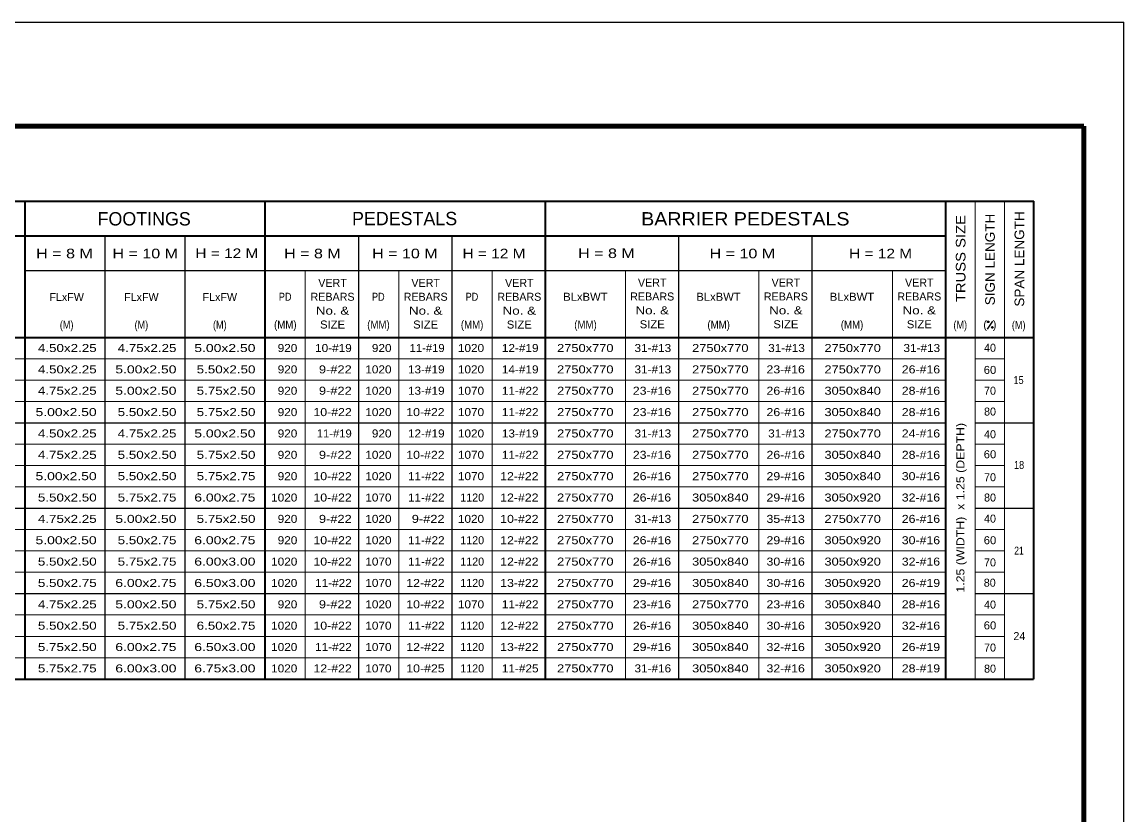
# Model space of a CAD drawing. Extents: x 312601.858 to 312602.699, y 144420.11 to 144420.704.
# Drawn here: x 312602.2859 to 312602.6989, y 144420.4066 to 144420.7036 of the extents above; entities that cross this region are included whole.
import ezdxf
from ezdxf.enums import TextEntityAlignment as Align

# ---------------------------------------------------------------- set-up
doc = ezdxf.new("R2010")
doc.units = 0
doc.header["$LTSCALE"] = 0.0012
for name, color, linetype, lineweight in [('1', 7, 'Continuous', 25), ('2', 7, 'Continuous', 13), ('39', 7, 'Continuous', 13)]:
    doc.layers.add(name, color=color, linetype=linetype, lineweight=lineweight)

msp = doc.modelspace()

# ---------------------------------------------------------------- linework, layer by layer
at = {"layer": '1', "lineweight": 35}
for p, q in [((312601.9241, 144420.6365), (312602.6651, 144420.6365)), ((312602.2871, 144420.4575), (312602.2871, 144420.6365)), ((312602.3771, 144420.4575), (312602.3771, 144420.6365)), ((312602.4821, 144420.4575), (312602.4821, 144420.6365)), ((312602.6321, 144420.4575), (312602.6321, 144420.6365)), ((312602.6651, 144420.4575), (312602.6651, 144420.6365)), ((312601.9571, 144420.6235), (312602.6321, 144420.6235)), ((312601.9241, 144420.5855), (312602.6651, 144420.5855)), ((312601.9241, 144420.4575), (312602.665, 144420.4575))]:
    msp.add_line(p, q, dxfattribs=at)
at = {"layer": '1', "lineweight": 13}
for p, q in [((312602.6431, 144420.4575), (312602.6431, 144420.6365)), ((312602.6541, 144420.4575), (312602.6541, 144420.6365)), ((312602.3921, 144420.4575), (312602.3921, 144420.6105)), ((312602.4271, 144420.4575), (312602.4271, 144420.6105)), ((312602.4621, 144420.4575), (312602.4621, 144420.6105)), ((312602.5121, 144420.4575), (312602.5121, 144420.6105)), ((312602.5621, 144420.4575), (312602.5621, 144420.6105)), ((312602.6121, 144420.4575), (312602.6121, 144420.6105)), ((312601.9571, 144420.5775), (312602.6321, 144420.5775)), ((312602.6431, 144420.5775), (312602.6541, 144420.5775)), ((312601.9573, 144420.5695), (312602.6321, 144420.5695)), ((312602.6431, 144420.5695), (312602.6541, 144420.5695)), ((312601.9573, 144420.5615), (312602.6321, 144420.5615)), ((312602.6431, 144420.5615), (312602.6541, 144420.5615)), ((312601.9573, 144420.5455), (312602.6321, 144420.5455)), ((312602.6431, 144420.5455), (312602.6541, 144420.5455)), ((312601.9573, 144420.5375), (312602.6321, 144420.5375)), ((312602.6431, 144420.5375), (312602.6541, 144420.5375)), ((312601.9573, 144420.5295), (312602.6321, 144420.5295)), ((312602.6431, 144420.5295), (312602.6541, 144420.5295)), ((312601.9573, 144420.5135), (312602.6321, 144420.5135)), ((312602.6431, 144420.5135), (312602.6541, 144420.5135)), ((312601.9573, 144420.5055), (312602.6321, 144420.5055)), ((312602.6431, 144420.5055), (312602.6541, 144420.5055)), ((312601.9573, 144420.4975), (312602.6321, 144420.4975)), ((312602.6431, 144420.4975), (312602.6541, 144420.4975)), ((312601.9573, 144420.4815), (312602.6321, 144420.4815)), ((312602.6431, 144420.4815), (312602.6541, 144420.4815)), ((312601.9573, 144420.4735), (312602.6321, 144420.4735)), ((312602.6431, 144420.4735), (312602.6541, 144420.4735)), ((312601.9573, 144420.4655), (312602.6321, 144420.4655)), ((312602.6431, 144420.4655), (312602.6541, 144420.4655))]:
    msp.add_line(p, q, dxfattribs=at)
at = {"layer": '1'}
for p, q in [((312602.3171, 144420.4575), (312602.3171, 144420.6235)), ((312602.3471, 144420.4575), (312602.3471, 144420.6235)), ((312602.4121, 144420.4575), (312602.4121, 144420.6235)), ((312602.4471, 144420.4575), (312602.4471, 144420.6235)), ((312602.5321, 144420.4575), (312602.5321, 144420.6235)), ((312602.5821, 144420.4575), (312602.5821, 144420.6235)), ((312602.2871, 144420.6105), (312602.6321, 144420.6105)), ((312602.6477, 144420.5886), (312602.6497, 144420.5916)), ((312601.9573, 144420.5535), (312602.6321, 144420.5535)), ((312602.6431, 144420.5535), (312602.6651, 144420.5535)), ((312601.9573, 144420.5215), (312602.6321, 144420.5215)), ((312602.6431, 144420.5215), (312602.6651, 144420.5215)), ((312601.9573, 144420.4895), (312602.6321, 144420.4895)), ((312602.6431, 144420.4895), (312602.6651, 144420.4895))]:
    msp.add_line(p, q, dxfattribs=at)
for centre in [(312602.648, 144420.5913), (312602.6496, 144420.5892)]:
    msp.add_circle(centre, 0.0003, dxfattribs=at)
at = {"layer": '39', "lineweight": 25}
for p, q in [((312601.8579, 144420.7036), (312602.6989, 144420.7036)), ((312602.5736, 144420.6646), (312602.6839, 144420.6646)), ((312602.6839, 144420.6515), (312602.6839, 144420.6646))]:
    msp.add_line(p, q, dxfattribs=at)
msp.add_lwpolyline([(312601.8579, 144420.1096), (312602.6989, 144420.1096), (312602.6989, 144420.7036)], dxfattribs=at)
at = {"layer": '39', "lineweight": 158}
for points in [[(312601.9089, 144420.1246), (312602.6839, 144420.1246), (312602.6839, 144420.6646)], [(312601.9089, 144420.1248), (312601.9089, 144420.6646), (312602.6839, 144420.6646)]]:
    msp.add_lwpolyline(points, dxfattribs=at)

# ---------------------------------------------------------------- texts
at = {"layer": '1'}
for s, height, p in [('PEDESTALS', 0.005, (312602.4293, 144420.6275)), ('FOOTINGS', 0.005, (312602.3317, 144420.6274)), ('VERT', 0.003, (312602.4023, 144420.6044)), ('VERT', 0.003, (312602.4372, 144420.6044)), ('VERT', 0.003, (312602.4723, 144420.6044)), ('VERT', 0.003, (312602.5221, 144420.6045)), ('VERT', 0.003, (312602.5722, 144420.6045)), ('VERT', 0.003, (312602.6222, 144420.6045)), ('FLxFW', 0.003, (312602.30265, 144420.5991)), ('FLxFW', 0.003, (312602.33065, 144420.5991)), ('FLxFW', 0.003, (312602.36005, 144420.5991)), ('REBARS', 0.003, (312602.4023, 144420.5992)), ('REBARS', 0.003, (312602.4372, 144420.5992)), ('REBARS', 0.003, (312602.4723, 144420.5992)), ('REBARS', 0.003, (312602.5221, 144420.5993)), ('REBARS', 0.003, (312602.5722, 144420.5993)), ('REBARS', 0.003, (312602.6222, 144420.5993)), ('(  )', 0.003, (312602.64865, 144420.5888)), ('40', 0.003, (312602.6487, 144420.5801)), ('70', 0.003, (312602.6487, 144420.564)), ('80', 0.003, (312602.6487, 144420.5562)), ('40', 0.003, (312602.6487, 144420.5477)), ('70', 0.003, (312602.6487, 144420.5316)), ('80', 0.003, (312602.6487, 144420.524)), ('40', 0.003, (312602.6487, 144420.5161)), ('70', 0.003, (312602.6487, 144420.4997)), ('80', 0.003, (312602.6486, 144420.4921)), ('40', 0.003, (312602.6487, 144420.4839)), ('24', 0.003, (312602.6597, 144420.4721)), ('70', 0.003, (312602.6487, 144420.4678)), ('80', 0.003, (312602.6487, 144420.4599))]:
    msp.add_text(s, height=height, dxfattribs=at).set_placement(p, align=Align.CENTER)
for s, height, width, p in [('BARRIER PEDESTALS', 0.005, 1.1, (312602.557, 144420.6274)), ('H = 8 M', 0.0036, 1.25, (312602.30185, 144420.6151)), ('H = 10 M', 0.0036, 1.25, (312602.3321, 144420.6151)), ('H = 12 M', 0.0036, 1.2, (312602.3627, 144420.6152)), ('H = 8 M', 0.0036, 1.25, (312602.39475, 144420.6151)), ('H = 10 M', 0.0036, 1.25, (312602.4294, 144420.6151)), ('H = 12 M', 0.0036, 1.2, (312602.4628, 144420.6151)), ('H = 8 M', 0.0036, 1.25, (312602.50495, 144420.6152)), ('H = 10 M', 0.0036, 1.25, (312602.5559, 144420.6151)), ('H = 12 M', 0.0036, 1.2, (312602.6077, 144420.6151)), ('PD', 0.003, 0.85, (312602.38455, 144420.5992)), ('PD', 0.003, 0.85, (312602.41945, 144420.5992)), ('PD', 0.003, 0.85, (312602.45455, 144420.5992)), ('BLxBWT', 0.003, 1.05, (312602.49705, 144420.5992)), ('BLxBWT', 0.003, 1.05, (312602.54695, 144420.5992)), ('BLxBWT', 0.003, 1.05, (312602.59695, 144420.5992)), ('No. &', 0.003, 1.25, (312602.4023, 144420.594)), ('No. &', 0.003, 1.25, (312602.4372, 144420.594)), ('No. &', 0.003, 1.25, (312602.4723, 144420.594)), ('No. &', 0.003, 1.25, (312602.5221, 144420.5941)), ('No. &', 0.003, 1.25, (312602.5722, 144420.5941)), ('No. &', 0.003, 1.25, (312602.6222, 144420.5941)), ('(M)', 0.003, 0.85, (312602.30265, 144420.5887)), ('(M)', 0.003, 0.85, (312602.33065, 144420.5887)), ('(M)', 0.003, 0.85, (312602.36005, 144420.5887)), ('(MM)', 0.003, 0.9, (312602.3846, 144420.5888)), ('SIZE', 0.003, 1.05, (312602.4023, 144420.5888)), ('(MM)', 0.003, 0.9, (312602.4195, 144420.5888)), ('SIZE', 0.003, 1.05, (312602.4372, 144420.5888)), ('(MM)', 0.003, 0.9, (312602.4546, 144420.5888)), ('SIZE', 0.003, 1.05, (312602.4723, 144420.5888)), ('(MM)', 0.003, 0.9, (312602.4971, 144420.5888)), ('SIZE', 0.003, 1.05, (312602.5221, 144420.5889)), ('(MM)', 0.003, 0.9, (312602.547, 144420.5888)), ('SIZE', 0.003, 1.05, (312602.5722, 144420.5889)), ('(MM)', 0.003, 0.9, (312602.597, 144420.5888)), ('SIZE', 0.003, 1.05, (312602.6222, 144420.5889)), ('(M)', 0.003, 0.85, (312602.63755, 144420.5887)), ('(M)', 0.003, 0.85, (312602.65945, 144420.5886)), ('60', 0.003, 1.05, (312602.6487, 144420.5718)), ('15', 0.003, 0.85, (312602.6594, 144420.568)), ('60', 0.003, 1.05, (312602.6487, 144420.5402)), ('18', 0.003, 0.85, (312602.6596, 144420.5362)), ('60', 0.003, 1.05, (312602.6487, 144420.508)), ('21', 0.003, 0.8, (312602.65955, 144420.5041)), ('60', 0.003, 1.05, (312602.6487, 144420.4761))]:
    msp.add_text(s, height=height, dxfattribs=dict(at, width=width)).set_placement(p, align=Align.CENTER)
for s, height, width, p in [('TRUSS SIZE', 0.0036, 1.15, (312602.6395, 144420.615)), ('SIGN LENGTH', 0.0036, 1.05, (312602.6505, 144420.61465)), ('SPAN LENGTH', 0.0036, 1.05, (312602.6615, 144420.61485)), ('1.25 (WIDTH)  x 1.25 (DEPTH) ', 0.003, 1.15, (312602.6391, 144420.5223))]:
    msp.add_text(s, height=height, rotation=90, dxfattribs=dict(at, width=width)).set_placement(p, align=Align.CENTER)
at = {"layer": '2'}
for s, width, p in [('4.50x2.25', 1.25, (312602.3139, 144420.58)), ('4.75x2.25', 1.25, (312602.3438, 144420.58)), ('5.00x2.50', 1.3, (312602.3734, 144420.58)), ('920', 1.1, (312602.3891, 144420.58)), ('10-#19', 1.1, (312602.4095, 144420.58)), ('920', 1.1, (312602.4244, 144420.58)), ('11-#19', 1.05, (312602.4443, 144420.58)), ('1020', 1.1, (312602.4591, 144420.58)), ('12-#19', 1.1, (312602.4795, 144420.58)), ('2750x770', 1.2, (312602.5076, 144420.58)), ('31-#13', 1.1, (312602.5292, 144420.58)), ('2750x770', 1.2, (312602.5582, 144420.58)), ('31-#13', 1.1, (312602.5793, 144420.58)), ('2750x770', 1.2, (312602.6078, 144420.58)), ('31-#13', 1.1, (312602.63, 144420.58)), ('4.50x2.25', 1.25, (312602.3139, 144420.572)), ('5.00x2.50', 1.3, (312602.3438, 144420.572)), ('5.50x2.50', 1.25, (312602.3734, 144420.572)), ('920', 1.1, (312602.3891, 144420.572)), ('9-#22', 1.2, (312602.4095, 144420.572)), ('1020', 1.1, (312602.4244, 144420.572)), ('13-#19', 1.1, (312602.4443, 144420.572)), ('1020', 1.1, (312602.4591, 144420.572)), ('14-#19', 1.1, (312602.4795, 144420.572)), ('2750x770', 1.2, (312602.5076, 144420.572)), ('31-#13', 1.1, (312602.5292, 144420.572)), ('2750x770', 1.2, (312602.5582, 144420.572)), ('23-#16', 1.15, (312602.5793, 144420.572)), ('2750x770', 1.2, (312602.6078, 144420.572)), ('26-#16', 1.15, (312602.63, 144420.572)), ('4.75x2.25', 1.25, (312602.3139, 144420.564)), ('5.00x2.50', 1.3, (312602.3438, 144420.564)), ('5.75x2.50', 1.25, (312602.3734, 144420.564)), ('920', 1.1, (312602.3891, 144420.564)), ('9-#22', 1.2, (312602.4095, 144420.564)), ('1020', 1.1, (312602.4244, 144420.564)), ('13-#19', 1.1, (312602.4443, 144420.564)), ('1070', 1.1, (312602.4591, 144420.564)), ('11-#22', 1.1, (312602.4795, 144420.564)), ('2750x770', 1.2, (312602.5076, 144420.564)), ('23-#16', 1.15, (312602.5292, 144420.564)), ('2750x770', 1.2, (312602.5582, 144420.564)), ('26-#16', 1.15, (312602.5793, 144420.564)), ('3050x840', 1.2, (312602.6078, 144420.564)), ('28-#16', 1.15, (312602.63, 144420.564)), ('5.00x2.50', 1.3, (312602.3139, 144420.556)), ('5.50x2.50', 1.25, (312602.3438, 144420.556)), ('5.75x2.50', 1.25, (312602.3734, 144420.556)), ('920', 1.1, (312602.3891, 144420.556)), ('10-#22', 1.15, (312602.4095, 144420.556)), ('1020', 1.1, (312602.4244, 144420.556)), ('10-#22', 1.15, (312602.4443, 144420.556)), ('1070', 1.1, (312602.4591, 144420.556)), ('11-#22', 1.1, (312602.4795, 144420.556)), ('2750x770', 1.2, (312602.5076, 144420.556)), ('23-#16', 1.15, (312602.5292, 144420.556)), ('2750x770', 1.2, (312602.5582, 144420.556)), ('26-#16', 1.15, (312602.5793, 144420.556)), ('3050x840', 1.2, (312602.6078, 144420.556)), ('28-#16', 1.15, (312602.63, 144420.556)), ('4.50x2.25', 1.25, (312602.3139, 144420.548)), ('4.75x2.25', 1.25, (312602.3438, 144420.548)), ('5.00x2.50', 1.3, (312602.3734, 144420.548)), ('920', 1.1, (312602.3891, 144420.548)), ('11-#19', 1.05, (312602.4095, 144420.548)), ('920', 1.1, (312602.4244, 144420.548)), ('12-#19', 1.1, (312602.4443, 144420.548)), ('1020', 1.1, (312602.4591, 144420.548)), ('13-#19', 1.1, (312602.4795, 144420.548)), ('2750x770', 1.2, (312602.5076, 144420.548)), ('31-#13', 1.1, (312602.5292, 144420.548)), ('2750x770', 1.2, (312602.5582, 144420.548)), ('31-#13', 1.1, (312602.5793, 144420.548)), ('2750x770', 1.2, (312602.6078, 144420.548)), ('24-#16', 1.15, (312602.63, 144420.548)), ('4.75x2.25', 1.25, (312602.3139, 144420.54)), ('5.50x2.50', 1.25, (312602.3438, 144420.54)), ('5.75x2.50', 1.25, (312602.3734, 144420.54)), ('920', 1.1, (312602.3891, 144420.54)), ('9-#22', 1.2, (312602.4095, 144420.54)), ('1020', 1.1, (312602.4244, 144420.54)), ('10-#22', 1.15, (312602.4443, 144420.54)), ('1070', 1.1, (312602.4591, 144420.54)), ('11-#22', 1.1, (312602.4795, 144420.54)), ('2750x770', 1.2, (312602.5076, 144420.54)), ('23-#16', 1.15, (312602.5292, 144420.54)), ('2750x770', 1.2, (312602.5582, 144420.54)), ('26-#16', 1.15, (312602.5793, 144420.54)), ('3050x840', 1.2, (312602.6078, 144420.54)), ('28-#16', 1.15, (312602.63, 144420.54)), ('5.00x2.50', 1.3, (312602.3139, 144420.532)), ('5.50x2.50', 1.25, (312602.3438, 144420.532)), ('5.75x2.75', 1.25, (312602.3734, 144420.532)), ('920', 1.1, (312602.3891, 144420.532)), ('10-#22', 1.15, (312602.4095, 144420.532)), ('1020', 1.1, (312602.4244, 144420.532)), ('11-#22', 1.1, (312602.4443, 144420.532)), ('1070', 1.1, (312602.4591, 144420.532)), ('12-#22', 1.15, (312602.4795, 144420.532)), ('2750x770', 1.2, (312602.5076, 144420.532)), ('26-#16', 1.15, (312602.5292, 144420.532)), ('2750x770', 1.2, (312602.5582, 144420.532)), ('29-#16', 1.15, (312602.5793, 144420.532)), ('3050x840', 1.2, (312602.6078, 144420.532)), ('30-#16', 1.15, (312602.63, 144420.532)), ('5.50x2.50', 1.25, (312602.3139, 144420.524)), ('5.75x2.75', 1.25, (312602.3438, 144420.524)), ('6.00x2.75', 1.3, (312602.3734, 144420.524)), ('1020', 1.1, (312602.3891, 144420.524)), ('10-#22', 1.15, (312602.4095, 144420.524)), ('1070', 1.1, (312602.4244, 144420.524)), ('11-#22', 1.1, (312602.4443, 144420.524)), ('12-#22', 1.15, (312602.4795, 144420.524)), ('2750x770', 1.2, (312602.5076, 144420.524)), ('26-#16', 1.15, (312602.5292, 144420.524)), ('3050x840', 1.2, (312602.5582, 144420.524)), ('29-#16', 1.15, (312602.5793, 144420.524)), ('3050x920', 1.2, (312602.6078, 144420.524)), ('32-#16', 1.15, (312602.63, 144420.524)), ('4.75x2.25', 1.25, (312602.3139, 144420.516)), ('5.00x2.50', 1.3, (312602.3438, 144420.516)), ('5.75x2.50', 1.25, (312602.3734, 144420.516)), ('920', 1.1, (312602.3891, 144420.516)), ('9-#22', 1.2, (312602.4095, 144420.516)), ('1020', 1.1, (312602.4244, 144420.516)), ('9-#22', 1.2, (312602.4443, 144420.516)), ('1020', 1.1, (312602.4591, 144420.516)), ('10-#22', 1.15, (312602.4795, 144420.516)), ('2750x770', 1.2, (312602.5076, 144420.516)), ('31-#13', 1.1, (312602.5292, 144420.516)), ('2750x770', 1.2, (312602.5582, 144420.516)), ('35-#13', 1.15, (312602.5793, 144420.516)), ('2750x770', 1.2, (312602.6078, 144420.516)), ('26-#16', 1.15, (312602.63, 144420.516)), ('5.00x2.50', 1.3, (312602.3139, 144420.508)), ('5.50x2.75', 1.25, (312602.3438, 144420.508)), ('6.00x2.75', 1.3, (312602.3734, 144420.508)), ('920', 1.1, (312602.3891, 144420.508)), ('10-#22', 1.15, (312602.4095, 144420.508)), ('1020', 1.1, (312602.4244, 144420.508)), ('11-#22', 1.1, (312602.4443, 144420.508)), ('12-#22', 1.15, (312602.4795, 144420.508)), ('2750x770', 1.2, (312602.5076, 144420.508)), ('26-#16', 1.15, (312602.5292, 144420.508)), ('2750x770', 1.2, (312602.5582, 144420.508)), ('29-#16', 1.15, (312602.5793, 144420.508)), ('3050x920', 1.2, (312602.6078, 144420.508)), ('30-#16', 1.15, (312602.63, 144420.508)), ('5.50x2.50', 1.25, (312602.3139, 144420.5)), ('5.75x2.75', 1.25, (312602.3438, 144420.5)), ('6.00x3.00', 1.3, (312602.3734, 144420.5)), ('1020', 1.1, (312602.3891, 144420.5)), ('10-#22', 1.15, (312602.4095, 144420.5)), ('1070', 1.1, (312602.4244, 144420.5)), ('11-#22', 1.1, (312602.4443, 144420.5)), ('12-#22', 1.15, (312602.4795, 144420.5)), ('2750x770', 1.2, (312602.5076, 144420.5)), ('26-#16', 1.15, (312602.5292, 144420.5)), ('3050x840', 1.2, (312602.5582, 144420.5)), ('30-#16', 1.15, (312602.5793, 144420.5)), ('3050x920', 1.2, (312602.6078, 144420.5)), ('32-#16', 1.15, (312602.63, 144420.5)), ('5.50x2.75', 1.25, (312602.3139, 144420.492)), ('6.00x2.75', 1.3, (312602.3438, 144420.492)), ('6.50x3.00', 1.3, (312602.3734, 144420.492)), ('1020', 1.1, (312602.3891, 144420.492)), ('11-#22', 1.1, (312602.4095, 144420.492)), ('1070', 1.1, (312602.4244, 144420.492)), ('12-#22', 1.15, (312602.4443, 144420.492)), ('13-#22', 1.15, (312602.4795, 144420.492)), ('2750x770', 1.2, (312602.5076, 144420.492)), ('29-#16', 1.15, (312602.5292, 144420.492)), ('3050x840', 1.2, (312602.5582, 144420.492)), ('30-#16', 1.15, (312602.5793, 144420.492)), ('3050x920', 1.2, (312602.6078, 144420.492)), ('26-#19', 1.15, (312602.63, 144420.492)), ('4.75x2.25', 1.25, (312602.3139, 144420.484)), ('5.00x2.50', 1.3, (312602.3438, 144420.484)), ('5.75x2.50', 1.25, (312602.3734, 144420.484)), ('920', 1.1, (312602.3891, 144420.484)), ('9-#22', 1.2, (312602.4095, 144420.484)), ('1020', 1.1, (312602.4244, 144420.484)), ('10-#22', 1.15, (312602.4443, 144420.484)), ('1070', 1.1, (312602.4591, 144420.484)), ('11-#22', 1.1, (312602.4795, 144420.484)), ('2750x770', 1.2, (312602.5076, 144420.484)), ('23-#16', 1.15, (312602.5292, 144420.484)), ('2750x770', 1.2, (312602.5582, 144420.484)), ('23-#16', 1.15, (312602.5793, 144420.484)), ('3050x840', 1.2, (312602.6078, 144420.484)), ('28-#16', 1.15, (312602.63, 144420.484)), ('5.50x2.50', 1.25, (312602.3139, 144420.476)), ('5.75x2.50', 1.25, (312602.3438, 144420.476)), ('6.50x2.75', 1.25, (312602.3734, 144420.476)), ('1020', 1.1, (312602.3891, 144420.476)), ('10-#22', 1.15, (312602.4095, 144420.476)), ('1070', 1.1, (312602.4244, 144420.476)), ('11-#22', 1.1, (312602.4443, 144420.476)), ('12-#22', 1.15, (312602.4795, 144420.476)), ('2750x770', 1.2, (312602.5076, 144420.476)), ('26-#16', 1.15, (312602.5292, 144420.476)), ('3050x840', 1.2, (312602.5582, 144420.476)), ('30-#16', 1.15, (312602.5793, 144420.476)), ('3050x920', 1.2, (312602.6078, 144420.476)), ('32-#16', 1.15, (312602.63, 144420.476)), ('5.75x2.50', 1.25, (312602.3139, 144420.468)), ('6.00x2.75', 1.3, (312602.3438, 144420.468)), ('6.50x3.00', 1.3, (312602.3734, 144420.468)), ('1020', 1.1, (312602.3891, 144420.468)), ('11-#22', 1.1, (312602.4095, 144420.468)), ('1070', 1.1, (312602.4244, 144420.468)), ('12-#22', 1.15, (312602.4443, 144420.468)), ('13-#22', 1.15, (312602.4795, 144420.468)), ('2750x770', 1.2, (312602.5076, 144420.468)), ('29-#16', 1.15, (312602.5292, 144420.468)), ('3050x840', 1.2, (312602.5582, 144420.468)), ('32-#16', 1.15, (312602.5793, 144420.468)), ('3050x920', 1.2, (312602.6078, 144420.468)), ('26-#19', 1.15, (312602.63, 144420.468)), ('5.75x2.75', 1.25, (312602.3139, 144420.46)), ('6.00x3.00', 1.3, (312602.3438, 144420.46)), ('6.75x3.00', 1.3, (312602.3734, 144420.46)), ('1020', 1.1, (312602.3891, 144420.46)), ('12-#22', 1.15, (312602.4095, 144420.46)), ('1070', 1.1, (312602.4244, 144420.46)), ('10-#25', 1.15, (312602.4443, 144420.46)), ('11-#25', 1.1, (312602.4795, 144420.46)), ('2750x770', 1.2, (312602.5076, 144420.46)), ('31-#16', 1.1, (312602.5292, 144420.46)), ('3050x840', 1.2, (312602.5582, 144420.46)), ('32-#16', 1.15, (312602.5793, 144420.46)), ('3050x920', 1.2, (312602.6078, 144420.46)), ('28-#19', 1.15, (312602.63, 144420.46))]:
    msp.add_text(s, height=0.003, dxfattribs=dict(at, width=width)).set_placement(p, align=Align.RIGHT)
for p in [(312602.4591, 144420.524), (312602.4591, 144420.508), (312602.4591, 144420.5), (312602.4591, 144420.492), (312602.4591, 144420.476), (312602.4591, 144420.468), (312602.4591, 144420.46)]:
    msp.add_text('1120', height=0.003, dxfattribs=at).set_placement(p, align=Align.RIGHT)

doc.saveas('drawing.dxf')
